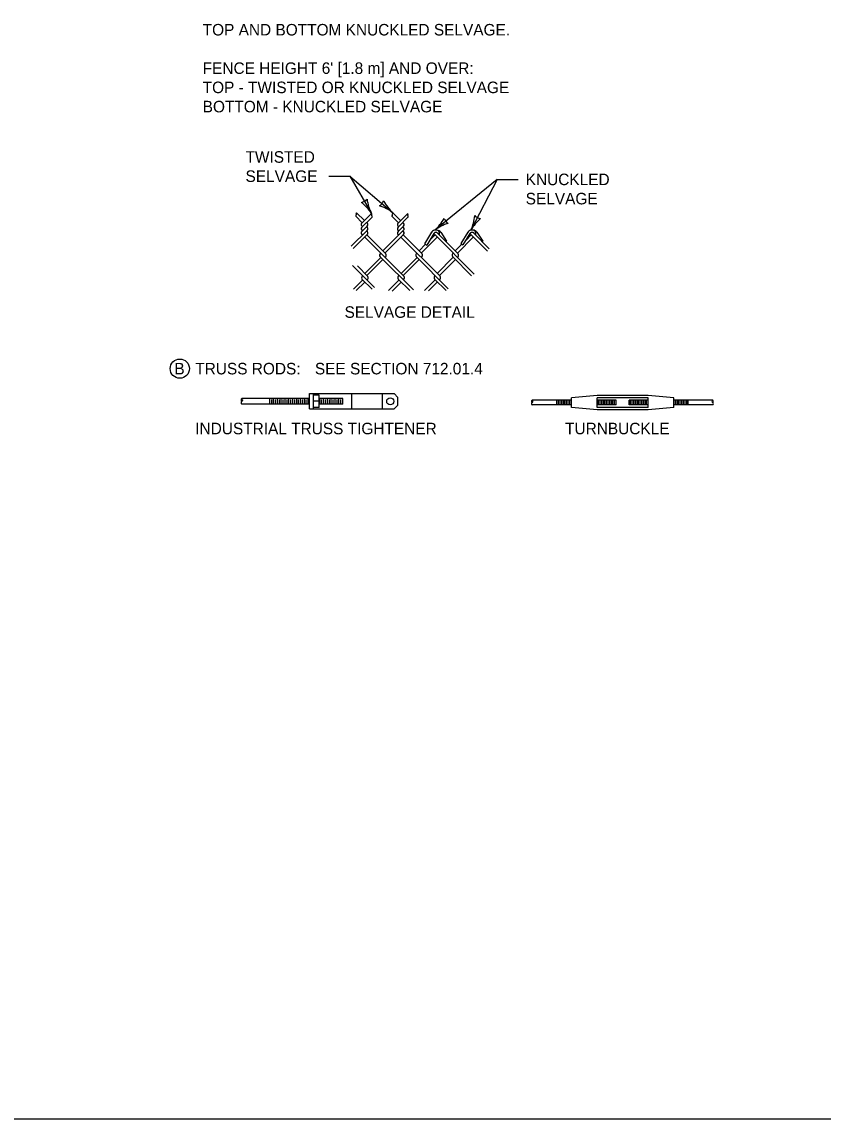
# Model space of a CAD drawing. Extents: x 49973.1 to 50021, y 49987.6 to 50015.4.
# Drawn here: x 50008.41 to 50012.58, y 49987.8 to 49993.51 of the extents above; entities that cross this region are included whole.
import ezdxf

# ---------------------------------------------------------------- set-up
doc = ezdxf.new("R2010")
doc.units = 0
for name, color, linetype in [('Level 1', 7, 'Continuous'), ('Level 2', 7, 'Continuous'), ('Level 3', 7, 'Continuous')]:
    doc.layers.add(name, color=color, linetype=linetype)

msp = doc.modelspace()

# ---------------------------------------------------------------- linework, layer by layer
at = {"layer": 'Level 1'}
for p, q in [((50010.1907, 49992.4742), (50010.1499, 49992.5148)), ((50010.3791, 49992.4744), (50010.3383, 49992.5152)), ((50010.3659, 49992.4612), (50010.4163, 49992.5118)), ((50010.1797, 49992.4632), (50010.1457, 49992.4968)), ((50010.1781, 49992.4615), (50010.2279, 49992.5114)), ((50010.1781, 49992.4397), (50010.2309, 49992.4926)), ((50010.3681, 49992.4632), (50010.3341, 49992.4972)), ((50010.3659, 49992.4394), (50010.4193, 49992.493)), ((50010.1223, 49992.3404), (50010.2055, 49992.4234)), ((50010.1325, 49992.3286), (50010.2055, 49992.4014)), ((50010.1781, 49992.4179), (50010.2055, 49992.4452)), ((50010.302, 49992.3009), (50010.2034, 49992.3993)), ((50010.2866, 49992.3162), (50010.3939, 49992.4236)), ((50010.2976, 49992.3053), (50010.3941, 49992.4016)), ((50010.3659, 49992.4176), (50010.3939, 49992.4456)), ((50010.4907, 49992.3008), (50010.3921, 49992.3996)), ((50010.5404, 49992.4135), (50010.5042, 49992.3539)), ((50010.5514, 49992.4068), (50010.5152, 49992.3472)), ((50010.5299, 49992.3713), (50010.5584, 49992.3999)), ((50010.7625, 49992.1956), (50010.5552, 49992.4031)), ((50010.6793, 49992.3008), (50010.5718, 49992.4084)), ((50010.5882, 49992.4132), (50010.6183, 49992.3667)), ((50010.7289, 49992.4138), (50010.6928, 49992.3542)), ((50010.7399, 49992.4069), (50010.7038, 49992.3475)), ((50010.7183, 49992.3714), (50010.7469, 49992.4)), ((50010.8319, 49992.3154), (50010.7445, 49992.4024)), ((50010.8411, 49992.3278), (50010.7605, 49992.4086)), ((50010.7767, 49992.4135), (50010.8069, 49992.367)), ((50010.3969, 49992.1838), (50010.1924, 49992.3883)), ((50010.5852, 49992.1843), (50010.3809, 49992.3884)), ((50010.475, 49992.3165), (50010.5093, 49992.3508)), ((50010.486, 49992.3055), (50010.5694, 49992.3888)), ((50010.5042, 49992.3539), (50010.5152, 49992.3472)), ((50010.6183, 49992.3667), (50010.6154, 49992.3648)), ((50010.6635, 49992.3166), (50010.6979, 49992.351)), ((50010.6746, 49992.3055), (50010.7581, 49992.3889)), ((50010.6928, 49992.3542), (50010.7038, 49992.3475)), ((50010.8069, 49992.367), (50010.8039, 49992.3651)), ((50010.4455, 49992.1132), (50010.2722, 49992.2863)), ((50010.6275, 49992.1198), (50010.4599, 49992.2878)), ((50010.7485, 49992.1876), (50010.6486, 49992.2877)), ((50010.2439, 49992.1262), (50010.1293, 49992.2406)), ((50010.2085, 49992.1836), (50010.1539, 49992.2382)), ((50010.1929, 49992.1992), (50010.2761, 49992.2824)), ((50010.2038, 49992.1883), (50010.287, 49992.2715)), ((50010.4648, 49992.2829), (50010.3813, 49992.1994)), ((50010.4758, 49992.2718), (50010.3923, 49992.1884)), ((50010.5698, 49992.1996), (50010.6532, 49992.2831)), ((50010.5808, 49992.1887), (50010.6643, 49992.2719)), ((50010.178, 49992.1699), (50010.2313, 49992.1166)), ((50010.3667, 49992.1698), (50010.4265, 49992.1098)), ((50010.555, 49992.1703), (50010.6155, 49992.1098)), ((50010.1341, 49992.117), (50010.1823, 49992.1656)), ((50010.1485, 49992.1096), (50010.1935, 49992.1544)), ((50010.3153, 49992.1102), (50010.3708, 49992.1656)), ((50010.3347, 49992.1074), (50010.3818, 49992.1546)), ((50010.5039, 49992.1104), (50010.5594, 49992.1659)), ((50010.5247, 49992.1092), (50010.5704, 49992.1549)), ((50009.9051, 49991.5488), (50009.5531, 49991.5488)), ((50009.6979, 49991.5189), (50009.6979, 49991.5488)), ((50009.7079, 49991.5239), (50009.7079, 49991.5438)), ((50009.7179, 49991.5189), (50009.7179, 49991.5488)), ((50009.728, 49991.5239), (50009.728, 49991.5438)), ((50009.738, 49991.5189), (50009.738, 49991.5488)), ((50009.748, 49991.5239), (50009.748, 49991.5438)), ((50009.758, 49991.5189), (50009.758, 49991.5488)), ((50009.768, 49991.5239), (50009.768, 49991.5438)), ((50009.778, 49991.5189), (50009.778, 49991.5488)), ((50009.788, 49991.5239), (50009.788, 49991.5438)), ((50009.798, 49991.5189), (50009.798, 49991.5488)), ((50009.808, 49991.5239), (50009.808, 49991.5438)), ((50009.818, 49991.5189), (50009.818, 49991.5488)), ((50009.828, 49991.5239), (50009.828, 49991.5438)), ((50009.838, 49991.5189), (50009.838, 49991.5488)), ((50009.8481, 49991.5239), (50009.8481, 49991.5438)), ((50009.8581, 49991.5189), (50009.8581, 49991.5488)), ((50009.8681, 49991.5239), (50009.8681, 49991.5438)), ((50009.8781, 49991.5189), (50009.8781, 49991.5488)), ((50009.8881, 49991.5239), (50009.8881, 49991.5438)), ((50009.8981, 49991.5189), (50009.8981, 49991.5488)), ((50009.9051, 49991.4939), (50009.9051, 49991.5739)), ((50009.9051, 49991.5739), (50010.3452, 49991.5739)), ((50009.9251, 49991.4939), (50009.9251, 49991.5739)), ((50009.9551, 49991.5661), (50009.9251, 49991.5661)), ((50009.9551, 49991.5016), (50009.9551, 49991.5661)), ((50010.0782, 49991.5488), (50009.9551, 49991.5488)), ((50009.9581, 49991.5189), (50009.9581, 49991.5488)), ((50009.9681, 49991.5239), (50009.9681, 49991.5438)), ((50009.9782, 49991.5189), (50009.9782, 49991.5488)), ((50009.9882, 49991.5239), (50009.9882, 49991.5438)), ((50009.9982, 49991.5189), (50009.9982, 49991.5488)), ((50010.0082, 49991.5239), (50010.0082, 49991.5438)), ((50010.0182, 49991.5189), (50010.0182, 49991.5488)), ((50010.0282, 49991.5239), (50010.0282, 49991.5438)), ((50010.0382, 49991.5189), (50010.0382, 49991.5488)), ((50010.0482, 49991.5239), (50010.0482, 49991.5438)), ((50010.0582, 49991.5189), (50010.0582, 49991.5488)), ((50010.0682, 49991.5239), (50010.0682, 49991.5438)), ((50010.0782, 49991.5189), (50010.0782, 49991.5488)), ((50010.1252, 49991.4939), (50010.1252, 49991.5739)), ((50010.2852, 49991.4939), (50010.2852, 49991.5739)), ((50010.3652, 49991.5539), (50010.3452, 49991.5739)), ((50010.3652, 49991.5138), (50010.3652, 49991.5539)), ((50011.4018, 49991.5646), (50011.2684, 49991.5521)), ((50011.2684, 49991.5022), (50011.2684, 49991.5521)), ((50011.6683, 49991.5646), (50011.4018, 49991.5646)), ((50011.6683, 49991.5521), (50011.4018, 49991.5521)), ((50011.4018, 49991.5022), (50011.4018, 49991.5521)), ((50011.8016, 49991.5521), (50011.6683, 49991.5646)), ((50011.6683, 49991.5022), (50011.6683, 49991.5521)), ((50011.8016, 49991.5022), (50011.8016, 49991.5521)), ((50009.9051, 49991.5189), (50009.5531, 49991.5189)), ((50009.9051, 49991.4939), (50010.3452, 49991.4939)), ((50009.9551, 49991.5339), (50009.9251, 49991.5339)), ((50009.9551, 49991.5016), (50009.9251, 49991.5016)), ((50010.0782, 49991.5189), (50009.9551, 49991.5189)), ((50010.3452, 49991.4939), (50010.3652, 49991.5138)), ((50011.2684, 49991.5397), (50011.064, 49991.5397)), ((50011.2684, 49991.5147), (50011.064, 49991.5147)), ((50011.1931, 49991.5147), (50011.1931, 49991.5397)), ((50011.2014, 49991.5189), (50011.2014, 49991.5355)), ((50011.2098, 49991.5147), (50011.2098, 49991.5397)), ((50011.2181, 49991.5189), (50011.2181, 49991.5355)), ((50011.2265, 49991.5147), (50011.2265, 49991.5397)), ((50011.2348, 49991.5189), (50011.2348, 49991.5355)), ((50011.2431, 49991.5147), (50011.2431, 49991.5397)), ((50011.2515, 49991.5189), (50011.2515, 49991.5355)), ((50011.2598, 49991.5147), (50011.2598, 49991.5397)), ((50011.2682, 49991.5147), (50011.2682, 49991.5397)), ((50011.4018, 49991.4898), (50011.2684, 49991.5022)), ((50011.5017, 49991.5397), (50011.4018, 49991.5397)), ((50011.5017, 49991.5147), (50011.4018, 49991.5147)), ((50011.6683, 49991.5022), (50011.4018, 49991.5022)), ((50011.6683, 49991.4898), (50011.4018, 49991.4898)), ((50011.4099, 49991.5189), (50011.4099, 49991.5355)), ((50011.4183, 49991.5147), (50011.4183, 49991.5397)), ((50011.4266, 49991.5189), (50011.4266, 49991.5355)), ((50011.435, 49991.5147), (50011.435, 49991.5397)), ((50011.4433, 49991.5189), (50011.4433, 49991.5355)), ((50011.4516, 49991.5147), (50011.4516, 49991.5397)), ((50011.46, 49991.5189), (50011.46, 49991.5355)), ((50011.4683, 49991.5147), (50011.4683, 49991.5397)), ((50011.4767, 49991.5189), (50011.4767, 49991.5355)), ((50011.485, 49991.5147), (50011.485, 49991.5397)), ((50011.4933, 49991.5189), (50011.4933, 49991.5355)), ((50011.5017, 49991.5147), (50011.5017, 49991.5397)), ((50011.5684, 49991.5147), (50011.5684, 49991.5397)), ((50011.6683, 49991.5397), (50011.5684, 49991.5397)), ((50011.6683, 49991.5147), (50011.5684, 49991.5147)), ((50011.5767, 49991.5189), (50011.5767, 49991.5355)), ((50011.5851, 49991.5147), (50011.5851, 49991.5397)), ((50011.5934, 49991.5189), (50011.5934, 49991.5355)), ((50011.6018, 49991.5147), (50011.6018, 49991.5397)), ((50011.6101, 49991.5189), (50011.6101, 49991.5355)), ((50011.6184, 49991.5147), (50011.6184, 49991.5397)), ((50011.6268, 49991.5189), (50011.6268, 49991.5355)), ((50011.6351, 49991.5147), (50011.6351, 49991.5397)), ((50011.6435, 49991.5189), (50011.6435, 49991.5355)), ((50011.6518, 49991.5147), (50011.6518, 49991.5397)), ((50011.6601, 49991.5189), (50011.6601, 49991.5355)), ((50011.8016, 49991.5022), (50011.6683, 49991.4898)), ((50012.004, 49991.5397), (50011.8016, 49991.5397)), ((50012.004, 49991.5147), (50011.8016, 49991.5147)), ((50011.8103, 49991.5147), (50011.8103, 49991.5397)), ((50011.8186, 49991.5189), (50011.8186, 49991.5355)), ((50011.8269, 49991.5147), (50011.8269, 49991.5397)), ((50011.8353, 49991.5189), (50011.8353, 49991.5355)), ((50011.8436, 49991.5147), (50011.8436, 49991.5397)), ((50011.852, 49991.5189), (50011.852, 49991.5355)), ((50011.8603, 49991.5147), (50011.8603, 49991.5397)), ((50011.8686, 49991.5189), (50011.8686, 49991.5355)), ((50011.877, 49991.5147), (50011.877, 49991.5397))]:
    msp.add_line(p, q, dxfattribs=at)
msp.add_lwpolyline([(49999.3835, 49998.9992), (50016.7501, 49998.9992), (50016.7501, 49987.7988), (49999.3835, 49987.7988)], close=True, dxfattribs=at)
msp.add_circle((50010.3252, 49991.5339), 0.0186, dxfattribs=at)
for centre, radius, start, end in [((50010.1845, 49992.4531), 0.0106, 127.2213, 252.3542), ((50010.1984, 49992.4531), 0.0107, 312.2096, 72.3602), ((50010.373, 49992.4533), 0.0106, 131.768, 252.3542), ((50010.3868, 49992.4534), 0.0106, 311.768, 72.5241), ((50010.1845, 49992.4313), 0.0106, 127.2123, 252.9837), ((50010.1845, 49992.4095), 0.0106, 127.0913, 253.484), ((50010.1985, 49992.4094), 0.0106, 311.768, 72.9575), ((50010.1984, 49992.4313), 0.0106, 311.768, 72.1401), ((50010.373, 49992.4315), 0.0106, 131.768, 252.3749), ((50010.373, 49992.4097), 0.0106, 131.768, 253.3071), ((50010.3869, 49992.4315), 0.0106, 311.768, 73.3071), ((50010.387, 49992.4096), 0.0106, 311.768, 73.3071), ((50010.5627, 49992.3978), 0.0273, 102.6734, 152.6316), ((50010.563, 49992.3981), 0.0145, 22.5638, 143.1414), ((50010.5683, 49992.413), 0.0164, 196.9635, 216.9745), ((50010.562, 49992.4019), 0.0231, 45.5211, 103.1567), ((50010.5678, 49992.3999), 0.0244, 32.7468, 89.8045), ((50010.5808, 49992.4174), 0.0127, 210.8209, 224.749), ((50010.5652, 49992.407), 0.0173, 334.228, 41.4854), ((50010.7512, 49992.3981), 0.0273, 102.6734, 152.1363), ((50010.7516, 49992.3984), 0.0145, 23.6873, 143.7804), ((50010.7568, 49992.4132), 0.0164, 196.9635, 221.5224), ((50010.7505, 49992.4022), 0.0231, 45.5211, 103.1567), ((50010.7563, 49992.4002), 0.0244, 32.9115, 89.8045), ((50010.77, 49992.4184), 0.0137, 212.1237, 226.0518), ((50010.7538, 49992.4072), 0.0173, 334.3309, 41.4854), ((50010.2834, 49992.294), 0.0136, 125.3746, 214.3714), ((50010.2906, 49992.2934), 0.0136, 305.1349, 33.1558), ((50010.4719, 49992.2942), 0.0136, 125.4672, 208.2379), ((50010.4791, 49992.2937), 0.0136, 305.1096, 31.6435), ((50010.6604, 49992.2945), 0.0136, 125.1268, 209.4398), ((50010.6676, 49992.2939), 0.0136, 305.3162, 30.272), ((50010.1897, 49992.177), 0.0136, 125.0516, 211.3361), ((50010.1968, 49992.1764), 0.0136, 305.6157, 31.3775), ((50010.3782, 49992.1772), 0.0136, 125.3233, 212.8295), ((50010.3853, 49992.1766), 0.0136, 305.3032, 31.3775), ((50010.5667, 49992.1774), 0.0136, 124.904, 211.6406), ((50010.5738, 49992.1768), 0.0136, 305.4781, 33.2216), ((50009.5571, 49991.5413), 0.00852, 118.42, 241.5809), ((50009.549, 49991.5413), 0.00852, 298.42, 61.5809), ((50009.5571, 49991.5264), 0.00852, 118.42, 241.5809), ((50011.0674, 49991.5334), 0.0071, 118.4196, 241.5804), ((50011.0674, 49991.5209), 0.0071, 118.4196, 241.5804), ((50011.0607, 49991.5334), 0.0071, 298.4196, 61.5804), ((50012.0074, 49991.5334), 0.0071, 118.3696, 241.5305), ((50012.0006, 49991.5334), 0.0071, 298.4206, 61.5814), ((50012.0006, 49991.521), 0.0071, 298.4206, 61.5814)]:
    msp.add_arc(centre, radius, start, end, dxfattribs=at)
for points in [[(50010.1499, 49992.5148), (50010.1481, 49992.5132), (50010.1485, 49992.5114), (50010.1481, 49992.5098), (50010.1467, 49992.508), (50010.1473, 49992.5068), (50010.1475, 49992.5044), (50010.1467, 49992.5034), (50010.1457, 49992.5024), (50010.1457, 49992.5008), (50010.1461, 49992.499), (50010.1457, 49992.4968)], [(50010.3383, 49992.5152), (50010.3369, 49992.5134), (50010.3369, 49992.5116), (50010.3365, 49992.51), (50010.3353, 49992.5082), (50010.3359, 49992.507), (50010.3359, 49992.5046), (50010.3351, 49992.5036), (50010.3341, 49992.5028), (50010.3345, 49992.501), (50010.3345, 49992.4992), (50010.3341, 49992.4972)], [(50010.4193, 49992.493), (50010.4193, 49992.4944), (50010.4181, 49992.4956), (50010.4187, 49992.4968), (50010.4191, 49992.4986), (50010.4181, 49992.5), (50010.4175, 49992.501), (50010.4169, 49992.5028), (50010.4179, 49992.504), (50010.4179, 49992.506), (50010.4175, 49992.5066), (50010.4169, 49992.5078), (50010.4167, 49992.5088), (50010.4169, 49992.5102), (50010.4163, 49992.5118)], [(50010.2309, 49992.4926), (50010.2307, 49992.4942), (50010.2297, 49992.4954), (50010.2303, 49992.4966), (50010.2307, 49992.4984), (50010.2297, 49992.4998), (50010.2291, 49992.5008), (50010.2285, 49992.5026), (50010.2295, 49992.5038), (50010.2295, 49992.5058), (50010.2291, 49992.5064), (50010.2285, 49992.5076), (50010.2279, 49992.5088), (50010.2285, 49992.51), (50010.2279, 49992.5114)]]:
    msp.add_spline(points, degree=3, dxfattribs=at)
at = {"layer": 'Level 2'}
msp.add_circle((50009.2292, 49991.7039), 0.05, dxfattribs=at)
at = {"layer": 'Level 3'}
for p, q in [((50010.0056, 49992.7054), (50010.115, 49992.7054)), ((50010.115, 49992.7054), (50010.2279, 49992.5114)), ((50010.115, 49992.7054), (50010.3383, 49992.5152)), ((50010.8811, 49992.6886), (50010.557, 49992.4247)), ((50010.8811, 49992.6886), (50010.7453, 49992.4247)), ((50010.8811, 49992.6886), (50010.9905, 49992.6886))]:
    msp.add_line(p, q, dxfattribs=at)
for centre, radius, start, end in [((50010.1634, 49992.6222), 0.0548, 282.3496, 318.0719), ((50010.4245, 49992.6152), 0.2223, 187.6668, 207.8503), ((50010.2407, 49992.5983), 0.0548, 301.7199, 337.4423), ((50010.4893, 49992.6783), 0.2223, 207.0371, 227.2206), ((50010.0326, 49992.3843), 0.233, 33.0381, 52.2879), ((50010.1962, 49992.3305), 0.233, 52.4084, 71.6583), ((50010.4098, 49992.5915), 0.2223, 311.4187, 331.6022), ((50010.6946, 49992.2368), 0.233, 106.9811, 126.2309), ((50010.6565, 49992.5055), 0.0548, 201.197, 236.9194), ((50010.5436, 49992.5182), 0.2223, 335.1144, 355.2979), ((50010.9469, 49992.3079), 0.233, 130.6767, 149.9266), ((50010.804, 49992.5387), 0.0548, 224.8927, 260.6151)]:
    msp.add_arc(centre, radius, start, end, dxfattribs=at)

# ---------------------------------------------------------------- texts
at = {"layer": 'Level 2'}
for s, p in [('TOP AND BOTTOM KNUCKLED SELVAGE.', (50009.3487, 49993.4375)), ("FENCE HEIGHT 6' [1.8 m] AND OVER:", (50009.3487, 49993.2375)), ('TOP - TWISTED OR KNUCKLED SELVAGE', (50009.3487, 49993.1375)), ('BOTTOM - KNUCKLED SELVAGE', (50009.3487, 49993.0375)), ('TWISTED', (50009.5717, 49992.7754)), ('SELVAGE', (50009.5717, 49992.6754)), ('KNUCKLED', (50011.0305, 49992.6586)), ('SELVAGE', (50011.0305, 49992.5586)), ('SELVAGE DETAIL', (50010.0872, 49991.9683)), ('B', (50009.2014, 49991.6739)), ('TRUSS RODS:', (50009.31, 49991.6739)), (' SEE SECTION 712.01.4', (50009.9106, 49991.6739)), ('INDUSTRIAL TRUSS TIGHTENER', (50009.31, 49991.3623)), ('TURNBUCKLE', (50011.2356, 49991.3623))]:
    msp.add_text(s, height=0.06, dxfattribs=at).set_placement(p)

doc.saveas('drawing.dxf')
